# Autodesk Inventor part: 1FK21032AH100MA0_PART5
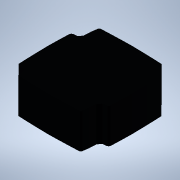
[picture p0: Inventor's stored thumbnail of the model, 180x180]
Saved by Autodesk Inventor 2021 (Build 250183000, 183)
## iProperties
Created: 2025-04
Part Number: 1FK21032AH100MA0_PART5
Material: Generic
Catalog Web Link: www.3dfindit.com
Description: -Servo synchronous motor
Document SubType Name: Modeling
Designer: psAdmin
Mass: 81.3964 g
Surface Area: 120.819 cm^2
Volume: 81.3964 cm^3
Density: 1 g/cm^3
Appearance: PSOLRGB-38-46-56
Category: PARTsolutions
Title: 1FK21032AH100MA0_PART5
Author: Cadenas PARTsolutions
Comments: Servo synchronous motor
Sending System: PARTsolutions
Preprocessor: ST-DEVELOPER v19.3
PSOL_IDENT_0: {$CADENAS_DATA/23d-libs/siemens_ag/_cat_/12/33/1fk21032ah100ma0.prj},213 {VTYP=3D},{NB=1FK21032AH100
PSOL_IDENT_1: MA0_PART5},{LINA=1FK21032AH100MA0_PART5},{NN=1FK21032AH100MA0_PART5},{NOPRJ=TRUE},{DATE=19.08.2025 1
PSOL_IDENT_2: 4:00:27},{GEOMDATE=30.07.2025 02:02:58},{VERSION=},{LINEID=10},{WBVAR=},{WBNUMERIC=}  {NB=1FK21032AH
PSOL_IDENT_3: 100MA0_PART5},{LINA=1FK21032AH100MA0_PART5},{KT=DUMMY},{PREVIEW=../../../_pool_/d3/78/p_d211_xx_0093
PSOL_IDENT_4: 4j.png},{DESCSHORT=SIMOTICS S-1FK2 HD, SINAMICS S210 3AC 400V-480V, 0.59 Nm, 4500 rpm},{DESCLONG=SIM
PSOL_IDENT_5: OTICS S-1FK2 HD servo motor M0=0.64 Nm; PN = 0.28 kW at nN=4500 rpm (380-480 V); PN = 0.167 kW at nN=
PSOL_IDENT_6: 2500 rpm (200-240 V); with holding brake; degree of protection IP64; cylindrical shaft D14 x 30 mm;
PSOL_IDENT_7: absolute encoder 22-bit + 12-bit multiturn (encoder AM22DQC); with OCC interface; plug size M17, rot
PSOL_IDENT_8: atable; SIMOTICS S-1FK2 servomotorfor a wide range of uses in industrial environments. SIMOTICS S‑1F
PSOL_IDENT_9: K2 servomotors are compact synchronous motors with a high dynamic performance that set themselves ap
PSOL_IDENT_10: art as a result of their high power density, degree of protection and overload capability. The motor
PSOL_IDENT_11: s are available in two variants: as High Dynamic variant (highest dynamic performance as a result of
PSOL_IDENT_12: the low intrinsic moment of inertia for applications demanding a high dynamic performance with low
PSOL_IDENT_13: moved masses) - and as Compact variant (precise and stable closed-loop control for medium up to larg
PSOL_IDENT_14: e moved masses as a result of a medium intrinsic moment of inertia). SIMOTICSS‑1FK2 servomotors full
PSOL_IDENT_15: y exploit their strengths in a system with the SINAMICSS210 frequency converter and simple connectio
PSOL_IDENT_16: n using the one cable connection (OCC). Advantages include the short control and positioning times,
PSOL_IDENT_17: fast and precise correction of disturbing quantities as well as stable control with a high dynamic p
PSOL_IDENT_18: erformance. The servo motors can be configured to address a wide range of requirements. For example
PSOL_IDENT_19: with and without holding brake, IP64 or IP65 degree of protection, singleturn or multiturn absolute
PSOL_IDENT_20: encoders - to name just a few. Further, the servomotors are available in different shaft heights ext
PSOL_IDENT_21: ending from 20 to 100. A shaft sealing ring is available to achieve an IP65 degree of protection and
PSOL_IDENT_22: for subsequent mounting at the motor or as spare part. SIMOTICS - the optimum motor for each and ev
PSOL_IDENT_23: ery motion control application.},{INTNO=195125315563},{SUPPLIERALTNO=1FK2103-2AH10-0MA0},{MANUID=1FK
PSOL_IDENT_24: 21032AH100MA0},{MANUNAME=Siemens},{MANUTYPEDESC=SYNCHRONOUS MOTOR 1FK2 HD 0,64 NM},{AAU732=SIMOTICS}
PSOL_IDENT_25: ,{AAO057=S-1FK2},{AAU734=SIMOTICS S-1FK2 HD servo motor M0=0.64 Nm; PN = 0.28 kW at nN=4500 rpm (380
PSOL_IDENT_26: -480 V); PN = 0.167 kW at nN=2500 rpm (200-240 V); with holding brake; degree of protection IP64; cy
PSOL_IDENT_27: lindrical shaft D14 x 30 mm; absolute encoder 22-bit + 12-bit multiturn (encoder AM22DQC); with OCC
PSOL_IDENT_28: interface; plug size M17, rotatable;},{AAW338=SYNCHRONOUS MOTOR 1FK2 HD 0,64 NM},{AAO742=SIMOTICS},{
PSOL_IDENT_29: AAO663=4034106444723},{NOCUPEROU=1},{PRICEQUANTITY=1},{QUANTITYMIN=1},{QUANTITYINT=1},{CTN=85015100}
PSOL_IDENT_30: ,{COO=RO},{AAO676=1FK2103-2AH10-0MA0},{AAO677=Siemens AG},{ORDERUNIT=C62},{CONTENTUNIT=C62}
NB: 1FK21032AH100MA0_PART5
NT: Servo synchronous motor
NBSYN: $MANUID._PART5
LINA: 1FK21032AH100MA0_PART5
CATALOG: SIEMENS
PREVIEW: ../../../_pool_/d3/78/p_d211_xx_00934j.png
DESCSHORT: SIMOTICS S-1FK2 HD, SINAMICS S210 3AC 400V-480V, 0.59 Nm, 4500 rpm
DESCLONG: SIMOTICS S-1FK2 HD servo motor M0=0.64 Nm; PN = 0.28 kW at nN=4500 rpm (380-480 V); PN = 0.167 kW at nN=2500 rpm (200-240 V); with holding brake; degree of prot
INTNO: 195125315563
SUPPLIERALTNO: 1FK2103-2AH10-0MA0
MANUID: 1FK21032AH100MA0
MANUNAME: Siemens
MANUTYPEDESC: SYNCHRONOUS MOTOR 1FK2 HD 0,64 NM
AAU732: SIMOTICS
AAO057: S-1FK2
AAU734: SIMOTICS S-1FK2 HD servo motor M0=0.64 Nm; PN = 0.28 kW at nN=4500 rpm (380-480 V); PN = 0.167 kW at nN=2500 rpm (200-240 V); with holding brake; degree of prot
AAW338: SYNCHRONOUS MOTOR 1FK2 HD 0,64 NM
AAO742: SIMOTICS
AAO663: 4034106444723.0
NOCUPEROU: 1
PRICEQUANTITY: 1
QUANTITYMIN: 1
QUANTITYINT: 1
CTN: 85015100
COO: RO
ARTICLENO: 1FK21032AH100MA0_PART5
BOMINFO: 1FK21032AH100MA0_PART5
CREATOR: CADENAS GmbH
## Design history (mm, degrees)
feature "2025_04_17_15_06_16_0611"
body "Solid1"
